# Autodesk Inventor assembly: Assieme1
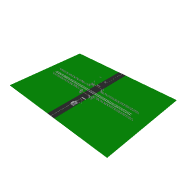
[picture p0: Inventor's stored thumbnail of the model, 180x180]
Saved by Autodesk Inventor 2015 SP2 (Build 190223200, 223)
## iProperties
Created: 2017-10
Part Number: Assieme1
Document SubType Name: Assembly
Designer: Massimo Pizzirani
Author: Massimo Pizzirani
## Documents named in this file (4)
- C:\Users\Massimo Pizzirani\Dropbox\THINX\P1041IT00\3D\Railway crossing\RAILWAY CROSSING.iam
- C:\Users\Massimo Pizzirani\Dropbox\THINX\P1041IT00\3D\Railway crossing\Binari.ipt
- C:\Users\Massimo Pizzirani\Dropbox\THINX\P1041IT00\3D\Railway crossing\Sbarra.ipt
- C:\Users\Massimo Pizzirani\Dropbox\THINX\P1041IT00\3D\Railway crossing\3d feroza.ipt
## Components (4 placed, 3 different names)
1. Binari:1 — Coincidente:1, Coincidente:2, Coincidente:3, Coincidente:4, Coincidente:5
2. Sbarra:1 — Coincidente:1, Coincidente:2
3. 3d feroza:1 — Coincidente:3
4. Sbarra:2 — Coincidente:4, Coincidente:5
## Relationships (5: Mate 5)
- Coincidente:1 [Mate]: Binari:1 ↔ Sbarra:1
- Coincidente:2 [Mate]: Binari:1 ↔ Sbarra:1
- Coincidente:3 [Mate]: Binari:1 ↔ 3d feroza:1
- Coincidente:4 [Mate]: Binari:1 ↔ Sbarra:2
- Coincidente:5 [Mate]: Binari:1 ↔ Sbarra:2
